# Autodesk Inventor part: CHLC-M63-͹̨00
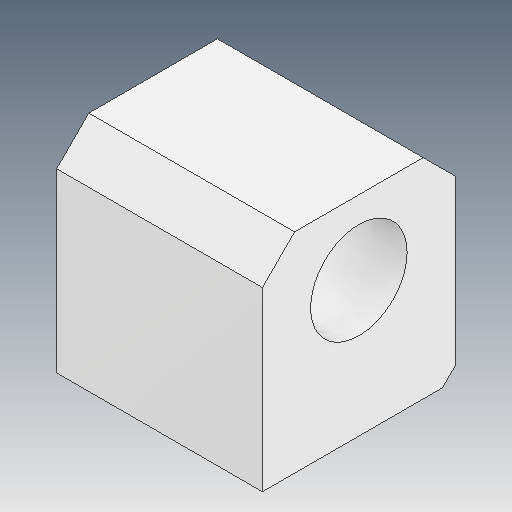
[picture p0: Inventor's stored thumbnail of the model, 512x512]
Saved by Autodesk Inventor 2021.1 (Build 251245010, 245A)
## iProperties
Created: 2021-05
Part Number: CHLC-M63-͹̨00
Material: Ogólny
Document SubType Name: Modeling
Designer: user
Density: 1 g/cm^3
Appearance: Domyślna
Author: user
Revision Number: ÈÎºÎ
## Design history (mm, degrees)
feature "Í¹Ì¨-À­Éì1"
node "Bryła1"
